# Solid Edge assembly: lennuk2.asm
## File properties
Author: Priit
Template: Normal.asm
Last saved by: Priit
Revision: 1
Application: Solid Edge
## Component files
lennuk1.par
mootor1.par
mootor1_mir1.par
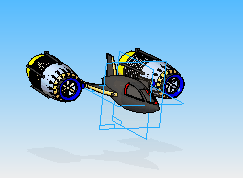
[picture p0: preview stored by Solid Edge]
